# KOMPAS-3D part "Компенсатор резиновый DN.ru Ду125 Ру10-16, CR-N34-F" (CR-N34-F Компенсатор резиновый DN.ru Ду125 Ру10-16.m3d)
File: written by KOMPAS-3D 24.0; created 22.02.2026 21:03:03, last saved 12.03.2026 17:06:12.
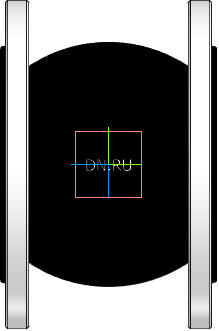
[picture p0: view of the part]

Document properties: Автор: DN.RU; Полное имя файла: CR-N34-F Компенсатор резиновый DN.ru Ду125 Ру10-16.cdw

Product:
- Body: Твердое тело2  | qty 1
    Масса: 21.558711
- Part/product: Компенсатор резиновый DN.ru Ду125 Ру10-16  | designation CR-N34-F
    Масса: 12
    Раздел спецификации: Прочие изделия
    Форматы листов документа: A2
    Комментарий: D140-02093
    Примечание: D140-02093
    additional columns: Типовые

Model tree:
1. Твердое тело2  (labels: Твердое тело2)

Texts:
  CR-N34-F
